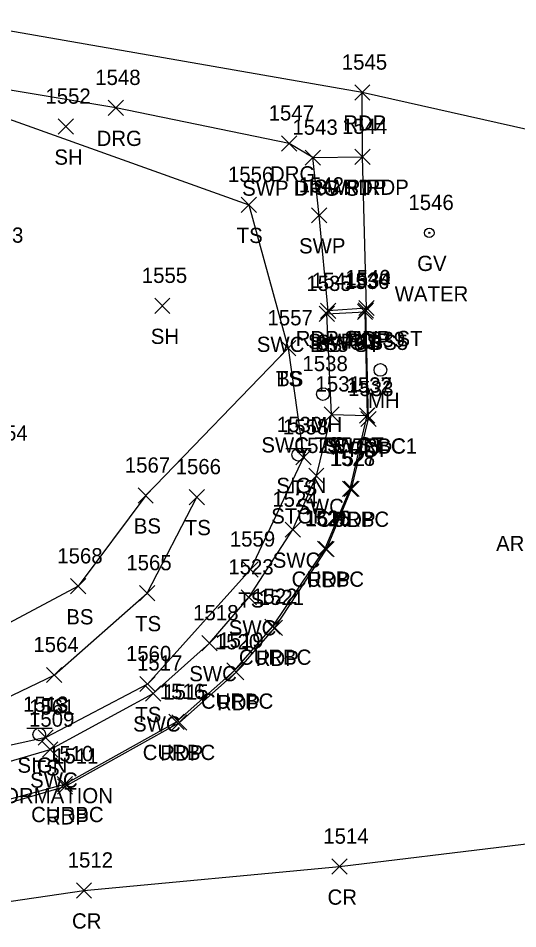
# Model space of a CAD drawing. Extents: x 1716490 to 1717645, y 888034 to 890004.
# Drawn here: x 1717449.9 to 1717515.4, y 888261.2 to 888380.7 of the extents above; entities that cross this region are included whole.
import ezdxf

# ---------------------------------------------------------------- set-up
doc = ezdxf.new("R2010")
doc.units = 0
for name, color, linetype in [('L_A', 7, 'Continuous'), ('L_I', 7, 'Continuous'), ('L_TIC', 7, 'Continuous'), ('LELB', 7, 'Continuous'), ('LSOGP', 7, 'Continuous'), ('P_A', 7, 'Continuous'), ('P_I', 7, 'Continuous'), ('P_TIC', 7, 'Continuous'), ('PET', 7, 'Continuous'), ('PRC', 7, 'Continuous'), ('R_A', 7, 'Continuous'), ('R_I', 7, 'Continuous'), ('R_TIC', 7, 'Continuous'), ('RC', 7, 'Continuous'), ('RDG', 7, 'Continuous'), ('RSW', 7, 'Continuous'), ('S_A', 7, 'Continuous'), ('S_C', 7, 'Continuous'), ('S_I', 7, 'Continuous'), ('SSGN', 7, 'Continuous'), ('U_A', 7, 'Continuous'), ('U_C', 7, 'Continuous'), ('U_I', 7, 'Continuous'), ('UUMH', 7, 'Continuous'), ('UWV', 7, 'Continuous')]:
    doc.layers.add(name, color=color, linetype=linetype)

msp = doc.modelspace()

# ---------------------------------------------------------------- linework, layer by layer
at = {"layer": 'L_TIC'}
for points in [[(1717455.12, 888365.47), (1717457.12, 888367.47)], [(1717457.12, 888365.47), (1717455.12, 888367.47)], [(1717479.12, 888355.2), (1717481.12, 888357.2)], [(1717481.12, 888355.2), (1717479.12, 888357.2)], [(1717467.77, 888341.96), (1717469.77, 888343.96)], [(1717469.77, 888341.96), (1717467.77, 888343.96)], [(1717489.36, 888340.91), (1717491.36, 888342.91)], [(1717491.36, 888340.91), (1717489.36, 888342.91)], [(1717494.36, 888341.17), (1717496.36, 888343.17)], [(1717496.36, 888341.17), (1717494.36, 888343.17)], [(1717484.27, 888336.4), (1717486.27, 888338.4)], [(1717486.27, 888336.4), (1717484.27, 888338.4)], [(1717484.27, 888336.4), (1717486.27, 888338.4)], [(1717486.27, 888336.4), (1717484.27, 888338.4)], [(1717489.99, 888327.72), (1717491.99, 888329.72)], [(1717491.99, 888327.72), (1717489.99, 888329.72)], [(1717494.63, 888327.58), (1717496.63, 888329.58)], [(1717496.63, 888327.58), (1717494.63, 888329.58)], [(1717486.29, 888322.09), (1717488.29, 888324.09)], [(1717488.29, 888322.09), (1717486.29, 888324.09)], [(1717465.59, 888317.08), (1717467.59, 888319.08)], [(1717467.59, 888317.08), (1717465.59, 888319.08)], [(1717472.31, 888316.87), (1717474.31, 888318.87)], [(1717474.31, 888316.87), (1717472.31, 888318.87)], [(1717479.33, 888307.38), (1717481.33, 888309.38)], [(1717481.33, 888307.38), (1717479.33, 888309.38)], [(1717456.73, 888305.17), (1717458.73, 888307.17)], [(1717458.73, 888305.17), (1717456.73, 888307.17)], [(1717465.79, 888304.27), (1717467.79, 888306.27)], [(1717467.79, 888304.27), (1717465.79, 888306.27)], [(1717453.59, 888293.53), (1717455.59, 888295.53)], [(1717455.59, 888293.53), (1717453.59, 888295.53)], [(1717465.83, 888292.35), (1717467.83, 888294.35)], [(1717467.83, 888292.35), (1717465.83, 888294.35)], [(1717452.47, 888285.33), (1717454.47, 888287.33)], [(1717454.47, 888285.33), (1717452.47, 888287.33)]]:
    msp.add_lwpolyline(points, dxfattribs=at)
at = {"layer": 'LELB'}
for points in [[(1717437.9, 888371.3), (1717480.12, 888356.2), (1717485.27, 888337.4), (1717487.29, 888323.09), (1717480.33, 888308.38), (1717466.83, 888293.35), (1717453.47, 888286.33), (1717437.38, 888282.78), (1717430.56, 888282.99)], [(1717490.36, 888341.91), (1717495.36, 888342.17)], [(1717485.27, 888337.4), (1717466.59, 888318.08), (1717457.73, 888306.17), (1717440.71, 888297.13), (1717432.39, 888300.02)], [(1717490.99, 888328.72), (1717495.63, 888328.58)], [(1717430.56, 888282.99), (1717454.59, 888294.53), (1717466.79, 888305.27), (1717473.31, 888317.87)]]:
    msp.add_lwpolyline(points, dxfattribs=at)
at = {"layer": 'LSOGP'}
msp.add_lwpolyline([(1717522.62, 888364.73), (1717495.01, 888370.94), (1717439.06, 888380.69), (1717439.62, 888372.79), (1717437.9, 888371.3), (1717447.29, 888348.24), (1717427.07, 888329.96), (1717421.68, 888328.92), (1717411.38, 888343.28), (1717406.07, 888347.48), (1717401.94, 888364.63), (1717397.44, 888368.91), (1717347.56, 888372.82)], dxfattribs=at)
at = {"layer": 'P_TIC'}
for points in [[(1717494.01, 888369.94), (1717496.01, 888371.94)], [(1717496.01, 888369.94), (1717494.01, 888371.94)], [(1717494.05, 888361.52), (1717496.05, 888363.52)], [(1717496.05, 888361.52), (1717494.05, 888363.52)], [(1717494.49, 888341.35), (1717496.49, 888343.35)], [(1717496.49, 888341.35), (1717494.49, 888343.35)], [(1717494.55, 888341.67), (1717496.55, 888343.67)], [(1717496.55, 888341.67), (1717494.55, 888343.67)], [(1717494.84, 888327.12), (1717496.84, 888329.12)], [(1717496.84, 888327.12), (1717494.84, 888329.12)], [(1717492.61, 888317.94), (1717494.61, 888319.94)], [(1717494.61, 888317.94), (1717492.61, 888319.94)], [(1717489.31, 888310.04), (1717491.31, 888312.04)], [(1717491.31, 888310.04), (1717489.31, 888312.04)], [(1717482.54, 888299.72), (1717484.54, 888301.72)], [(1717484.54, 888299.72), (1717482.54, 888301.72)], [(1717477.45, 888293.9), (1717479.45, 888295.9)], [(1717479.45, 888293.9), (1717477.45, 888295.9)], [(1717470.01, 888287.31), (1717472.01, 888289.31)], [(1717472.01, 888287.31), (1717470.01, 888289.31)], [(1717455, 888278.92), (1717457, 888280.92)], [(1717457, 888278.92), (1717455, 888280.92)], [(1717491.01, 888268.4), (1717493.01, 888270.4)], [(1717493.01, 888268.4), (1717491.01, 888270.4)], [(1717457.49, 888265.27), (1717459.49, 888267.27)], [(1717459.49, 888265.27), (1717457.49, 888267.27)]]:
    msp.add_lwpolyline(points, dxfattribs=at)
at = {"layer": 'PET'}
msp.add_lwpolyline([(1717429.44, 888275.7), (1717436.04, 888275.67), (1717444.58, 888276.58), (1717456, 888279.92), (1717471.01, 888288.31), (1717478.45, 888294.9), (1717483.54, 888300.72), (1717490.31, 888311.04), (1717493.61, 888318.94), (1717495.84, 888328.12), (1717495.49, 888342.35), (1717495.55, 888342.67), (1717495.05, 888362.52), (1717495.01, 888370.94)], dxfattribs=at)
at = {"layer": 'PRC'}
msp.add_lwpolyline([(1717436.1, 888262.99), (1717458.49, 888266.27), (1717492.01, 888269.4), (1717536.7, 888274.82), (1717555.46, 888275.73), (1717587.78, 888278.25), (1717619.44, 888277.12), (1717629.03, 888277.17)], dxfattribs=at)
at = {"layer": 'R_TIC'}
for points in [[(1717461.66, 888367.93), (1717463.66, 888369.93)], [(1717463.66, 888367.93), (1717461.66, 888369.93)], [(1717484.42, 888363.27), (1717486.42, 888365.27)], [(1717486.42, 888363.27), (1717484.42, 888365.27)], [(1717487.53, 888361.4), (1717489.53, 888363.4)], [(1717489.53, 888361.4), (1717487.53, 888363.4)], [(1717487.53, 888361.4), (1717489.53, 888363.4)], [(1717489.53, 888361.4), (1717487.53, 888363.4)], [(1717494.05, 888361.52), (1717496.05, 888363.52)], [(1717496.05, 888361.52), (1717494.05, 888363.52)], [(1717488.35, 888353.83), (1717490.35, 888355.83)], [(1717490.35, 888353.83), (1717488.35, 888355.83)], [(1717489.36, 888340.91), (1717491.36, 888342.91)], [(1717491.36, 888340.91), (1717489.36, 888342.91)], [(1717489.52, 888341.29), (1717491.52, 888343.29)], [(1717491.52, 888341.29), (1717489.52, 888343.29)], [(1717494.36, 888341.17), (1717496.36, 888343.17)], [(1717496.36, 888341.17), (1717494.36, 888343.17)], [(1717494.55, 888341.67), (1717496.55, 888343.67)], [(1717496.55, 888341.67), (1717494.55, 888343.67)], [(1717489.99, 888327.72), (1717491.99, 888329.72)], [(1717491.99, 888327.72), (1717489.99, 888329.72)], [(1717494.63, 888327.58), (1717496.63, 888329.58)], [(1717496.63, 888327.58), (1717494.63, 888329.58)], [(1717494.65, 888327.57), (1717496.65, 888329.57)], [(1717496.65, 888327.57), (1717494.65, 888329.57)], [(1717494.65, 888327.57), (1717496.65, 888329.57)], [(1717496.65, 888327.57), (1717494.65, 888329.57)], [(1717487.98, 888319.65), (1717489.98, 888321.65)], [(1717489.98, 888319.65), (1717487.98, 888321.65)], [(1717492.43, 888317.97), (1717494.43, 888319.97)], [(1717494.43, 888317.97), (1717492.43, 888319.97)], [(1717484.9, 888312.6), (1717486.9, 888314.6)], [(1717486.9, 888312.6), (1717484.9, 888314.6)], [(1717489.14, 888310.11), (1717491.14, 888312.11)], [(1717491.14, 888310.11), (1717489.14, 888312.11)], [(1717479.12, 888303.72), (1717481.12, 888305.72)], [(1717481.12, 888303.72), (1717479.12, 888305.72)], [(1717482.24, 888299.87), (1717484.24, 888301.87)], [(1717484.24, 888299.87), (1717482.24, 888301.87)], [(1717473.95, 888297.71), (1717475.95, 888299.71)], [(1717475.95, 888297.71), (1717473.95, 888299.71)], [(1717477.24, 888294.11), (1717479.24, 888296.11)], [(1717479.24, 888294.11), (1717477.24, 888296.11)], [(1717466.58, 888291.11), (1717468.58, 888293.11)], [(1717468.58, 888291.11), (1717466.58, 888293.11)], [(1717469.62, 888287.38), (1717471.62, 888289.38)], [(1717471.62, 888287.38), (1717469.62, 888289.38)], [(1717453.06, 888283.75), (1717455.06, 888285.75)], [(1717455.06, 888283.75), (1717453.06, 888285.75)], [(1717454.98, 888279.23), (1717456.98, 888281.23)], [(1717456.98, 888279.23), (1717454.98, 888281.23)]]:
    msp.add_lwpolyline(points, dxfattribs=at)
at = {"layer": 'RC'}
msp.add_lwpolyline([(1717435.94, 888275.99), (1717444.61, 888277.14), (1717455.98, 888280.23), (1717470.62, 888288.38), (1717478.24, 888295.11), (1717483.24, 888300.87), (1717490.14, 888311.11), (1717493.43, 888318.97), (1717495.63, 888328.58), (1717495.65, 888328.57)], dxfattribs=at)
at = {"layer": 'RDG'}
msp.add_lwpolyline([(1717488.53, 888362.4), (1717485.42, 888364.27), (1717462.66, 888368.93), (1717439.62, 888372.79), (1717439.06, 888380.69)], dxfattribs=at)
at = {"layer": 'RSW'}
for points in [[(1717495.55, 888342.67), (1717490.52, 888342.29), (1717489.35, 888354.83), (1717488.53, 888362.4), (1717495.05, 888362.52)], [(1717429.42, 888275.92), (1717429.11, 888280.08), (1717435.9, 888280.75), (1717443.41, 888281.64), (1717454.06, 888284.75), (1717467.58, 888292.11), (1717474.95, 888298.71), (1717480.12, 888304.72), (1717485.9, 888313.6), (1717488.98, 888320.65), (1717490.99, 888328.72), (1717490.36, 888341.91), (1717495.36, 888342.17), (1717495.65, 888328.57)]]:
    msp.add_lwpolyline(points, dxfattribs=at)
at = {"layer": 'SSGN'}
for p, q in [((1717484.96, 888324.25), (1717488.29, 888324.25)), ((1717486.6, 888323.42), (1717486.6, 888323.42)), ((1717450.99, 888287.56), (1717454.32, 888287.56)), ((1717452.63, 888286.73), (1717452.63, 888286.73))]:
    msp.add_line(p, q, dxfattribs=at)
for centre in [(1717486.6, 888323.42), (1717452.63, 888286.73)]:
    msp.add_circle(centre, 0.833, dxfattribs=at)
at = {"layer": 'UUMH'}
for p, q in [((1717497.38, 888334.56), (1717497.38, 888334.56)), ((1717498.22, 888334.56), (1717498.22, 888334.56)), ((1717489.85, 888331.39), (1717489.85, 888331.39)), ((1717490.68, 888331.39), (1717490.68, 888331.39))]:
    msp.add_line(p, q, dxfattribs=at)
for centre in [(1717497.38, 888334.56), (1717489.85, 888331.39)]:
    msp.add_circle(centre, 0.833, dxfattribs=at)
at = {"layer": 'UWV'}
for radius in [0.625, 0.0833]:
    msp.add_circle((1717503.8, 888352.53), radius, dxfattribs=at)

# ---------------------------------------------------------------- texts
at = {"layer": 'L_A'}
for s, p in [('SH', (1717454.61, 888361.47)), ('TS', (1717478.53, 888351.2)), ('SH', (1717467.26, 888337.96)), ('BS', (1717493.8, 888337.17)), ('BS', (1717488.8, 888336.91)), ('TS', (1717483.67, 888332.4)), ('BS', (1717483.71, 888332.4)), ('TS', (1717489.4, 888323.72)), ('TS', (1717494.04, 888323.58)), ('TS', (1717485.7, 888318.09)), ('BS', (1717465.03, 888313.08)), ('TS', (1717471.72, 888312.87)), ('TS', (1717478.74, 888303.38)), ('BS', (1717456.17, 888301.17)), ('TS', (1717465.2, 888300.27)), ('TS', (1717453, 888289.53)), ('TS', (1717465.23, 888288.35)), ('TS', (1717451.88, 888281.33))]:
    msp.add_text(s, height=2, dxfattribs=at).set_placement(p)
at = {"layer": 'L_I'}
for s, p in [('1552', (1717453.43, 888369.47)), ('1556', (1717477.38, 888359.2)), ('1553', (1717444.59, 888351.24)), ('1555', (1717466.08, 888345.96)), ('1535', (1717487.67, 888344.91)), ('1536', (1717492.61, 888345.17)), ('1557', (1717482.57, 888340.4)), ('1557', (1717482.57, 888340.4)), ('1531', (1717488.87, 888331.72)), ('1532', (1717492.94, 888331.58)), ('1554', (1717445.16, 888325.28)), ('1558', (1717484.59, 888326.09)), ('1567', (1717463.85, 888321.08)), ('1566', (1717470.52, 888320.87)), ('1559', (1717477.63, 888311.38)), ('1568', (1717454.99, 888309.17)), ('1565', (1717464.05, 888308.27)), ('1564', (1717451.85, 888297.53)), ('1560', (1717464, 888296.35)), ('1561', (1717451.3, 888289.33))]:
    msp.add_text(s, height=2, dxfattribs=at).set_placement(p)
at = {"layer": 'P_A'}
for s, p in [('RDP', (1717492.5, 888365.94)), ('RDP', (1717492.54, 888357.52)), ('RDP', (1717492.97, 888337.35)), ('RDP', (1717493.04, 888337.67)), ('RDP', (1717493.33, 888323.12)), ('RDP', (1717491.1, 888313.94)), ('RDP', (1717487.79, 888306.04)), ('RDP', (1717481.03, 888295.72)), ('RDP', (1717475.94, 888289.9)), ('RDP', (1717468.5, 888283.31)), ('RDP', (1717453.49, 888274.92)), ('CR', (1717490.45, 888264.4)), ('CR', (1717456.92, 888261.27))]:
    msp.add_text(s, height=2, dxfattribs=at).set_placement(p)
at = {"layer": 'P_I'}
for s, p in [('1545', (1717492.32, 888373.94)), ('1544', (1717492.35, 888365.52)), ('1540', (1717492.78, 888345.67)), ('1534', (1717492.79, 888345.35)), ('1533', (1717493.15, 888331.12)), ('1527', (1717490.92, 888321.94)), ('1526', (1717487.56, 888314.04)), ('1521', (1717481.42, 888303.72)), ('1520', (1717475.67, 888297.9)), ('1515', (1717468.89, 888291.31)), ('1511', (1717454.44, 888282.92)), ('1514', (1717489.89, 888272.4)), ('1512', (1717456.36, 888269.27))]:
    msp.add_text(s, height=2, dxfattribs=at).set_placement(p)
at = {"layer": 'R_A'}
for s, p in [('DRG', (1717460.15, 888363.93)), ('DRG', (1717482.9, 888359.27)), ('SWP RDP', (1717488.63, 888357.52)), ('SWP DRG ST', (1717479.25, 888357.4)), ('DRG', (1717486.02, 888357.4)), ('SWP', (1717486.71, 888349.83)), ('RDP SWP ST', (1717486.27, 888337.67)), ('SWP', (1717487.88, 888337.29)), ('SWC BS5', (1717488.99, 888337.17)), ('SWC BS5 ST', (1717481.17, 888336.91)), ('SWC TS5 ST', (1717481.77, 888323.72)), ('SWC CC1', (1717489.85, 888323.57)), ('CURBC', (1717491.22, 888323.58)), ('CURBC', (1717491.23, 888323.57)), ('SWC', (1717486.35, 888315.65)), ('CURBC', (1717489.02, 888313.97)), ('SWC', (1717483.26, 888308.6)), ('CURBC', (1717485.73, 888306.11)), ('SWC', (1717477.49, 888299.72)), ('CURBC', (1717478.82, 888295.87)), ('SWC', (1717472.31, 888293.71)), ('CURBC', (1717473.83, 888290.11)), ('SWC', (1717464.94, 888287.11)), ('CURBC', (1717466.2, 888283.38)), ('SWC', (1717451.43, 888279.75)), ('CURBC', (1717451.56, 888275.23))]:
    msp.add_text(s, height=2, dxfattribs=at).set_placement(p)
at = {"layer": 'R_I'}
for s, p in [('1548', (1717459.97, 888371.93)), ('1547', (1717482.72, 888367.27)), ('1543', (1717485.84, 888365.4)), ('1543', (1717485.84, 888365.4)), ('1544', (1717492.35, 888365.52)), ('1542', (1717486.66, 888357.83)), ('1540', (1717492.78, 888345.67)), ('1535', (1717487.67, 888344.91)), ('1541', (1717488.39, 888345.29)), ('1536', (1717492.61, 888345.17)), ('1531', (1717488.87, 888331.72)), ('1532', (1717492.94, 888331.58)), ('1537', (1717492.95, 888331.57)), ('1537', (1717492.95, 888331.57)), ('1529', (1717486.28, 888323.65)), ('1528', (1717490.74, 888321.97)), ('1524', (1717483.2, 888316.6)), ('1525', (1717487.45, 888314.11)), ('1523', (1717477.43, 888307.72)), ('1522', (1717480.55, 888303.87)), ('1518', (1717472.82, 888301.71)), ('1519', (1717476.11, 888298.11)), ('1517', (1717465.45, 888295.11)), ('1516', (1717468.44, 888291.38)), ('1509', (1717451.28, 888287.75)), ('1510', (1717453.77, 888283.23))]:
    msp.add_text(s, height=2, dxfattribs=at).set_placement(p)
at = {"layer": 'S_A'}
for p in [(1717483.74, 888318.4), (1717449.77, 888281.71)]:
    msp.add_text('SIGN', height=2, dxfattribs=at).set_placement(p)
at = {"layer": 'S_C'}
for s, p in [('STOP', (1717483.06, 888314.4)), ('ARROW LEFT / STOP', (1717512.56, 888310.78)), ('INFORMATION', (1717443.57, 888277.71))]:
    msp.add_text(s, height=2, dxfattribs=at).set_placement(p)
at = {"layer": 'S_I'}
for s, p in [('1530', (1717483.8, 888326.4)), ('1513', (1717450.49, 888289.71))]:
    msp.add_text(s, height=2, dxfattribs=at).set_placement(p)
at = {"layer": 'U_A'}
for s, p in [('GV', (1717502.21, 888347.53)), ('MH', (1717495.75, 888329.56)), ('MH', (1717488.21, 888326.39))]:
    msp.add_text(s, height=2, dxfattribs=at).set_placement(p)
at = {"layer": 'U_C'}
msp.add_text('WATER', height=2, dxfattribs=at).set_placement((1717499.26, 888343.53))
at = {"layer": 'U_I'}
for s, p in [('1546', (1717501.06, 888355.53)), ('1539', (1717494.68, 888337.56)), ('1538', (1717487.16, 888334.39))]:
    msp.add_text(s, height=2, dxfattribs=at).set_placement(p)

doc.saveas('drawing.dxf')
